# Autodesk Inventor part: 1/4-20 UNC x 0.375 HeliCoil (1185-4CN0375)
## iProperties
Title: 1/4-20 UNC x 0.375 HeliCoil (1185-4CN0375)
Author: CFitzwater
Shininess: 64.0
Angle Display Precision: 2
Document Length Units: 11272
Document Angle Units: 11286
Document Time Units: 11279
Document Mass Units: 11290
Document Length Units Precision: 3
Document Angle Units Precision: 2
Compacted: True
PropertySet Name: _Private Model Information
Created: 2002-02
Part Number: Helicoil-1185-CN
Material: Stainless Steel, Austenitic
Document SubType Name: Modeling
Designer: CFitzwater
Control State: 0
Master: False
Checked Out: False
PropertySet Name: Design Tracking Control
Density: 7.750000000000001
Volumn: 0.37239295650448834
Area: 5.5389113408432396
PropertySet Name: Model Information
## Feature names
1. Extrusion1
2. Chamfer1
3. Chamfer2
